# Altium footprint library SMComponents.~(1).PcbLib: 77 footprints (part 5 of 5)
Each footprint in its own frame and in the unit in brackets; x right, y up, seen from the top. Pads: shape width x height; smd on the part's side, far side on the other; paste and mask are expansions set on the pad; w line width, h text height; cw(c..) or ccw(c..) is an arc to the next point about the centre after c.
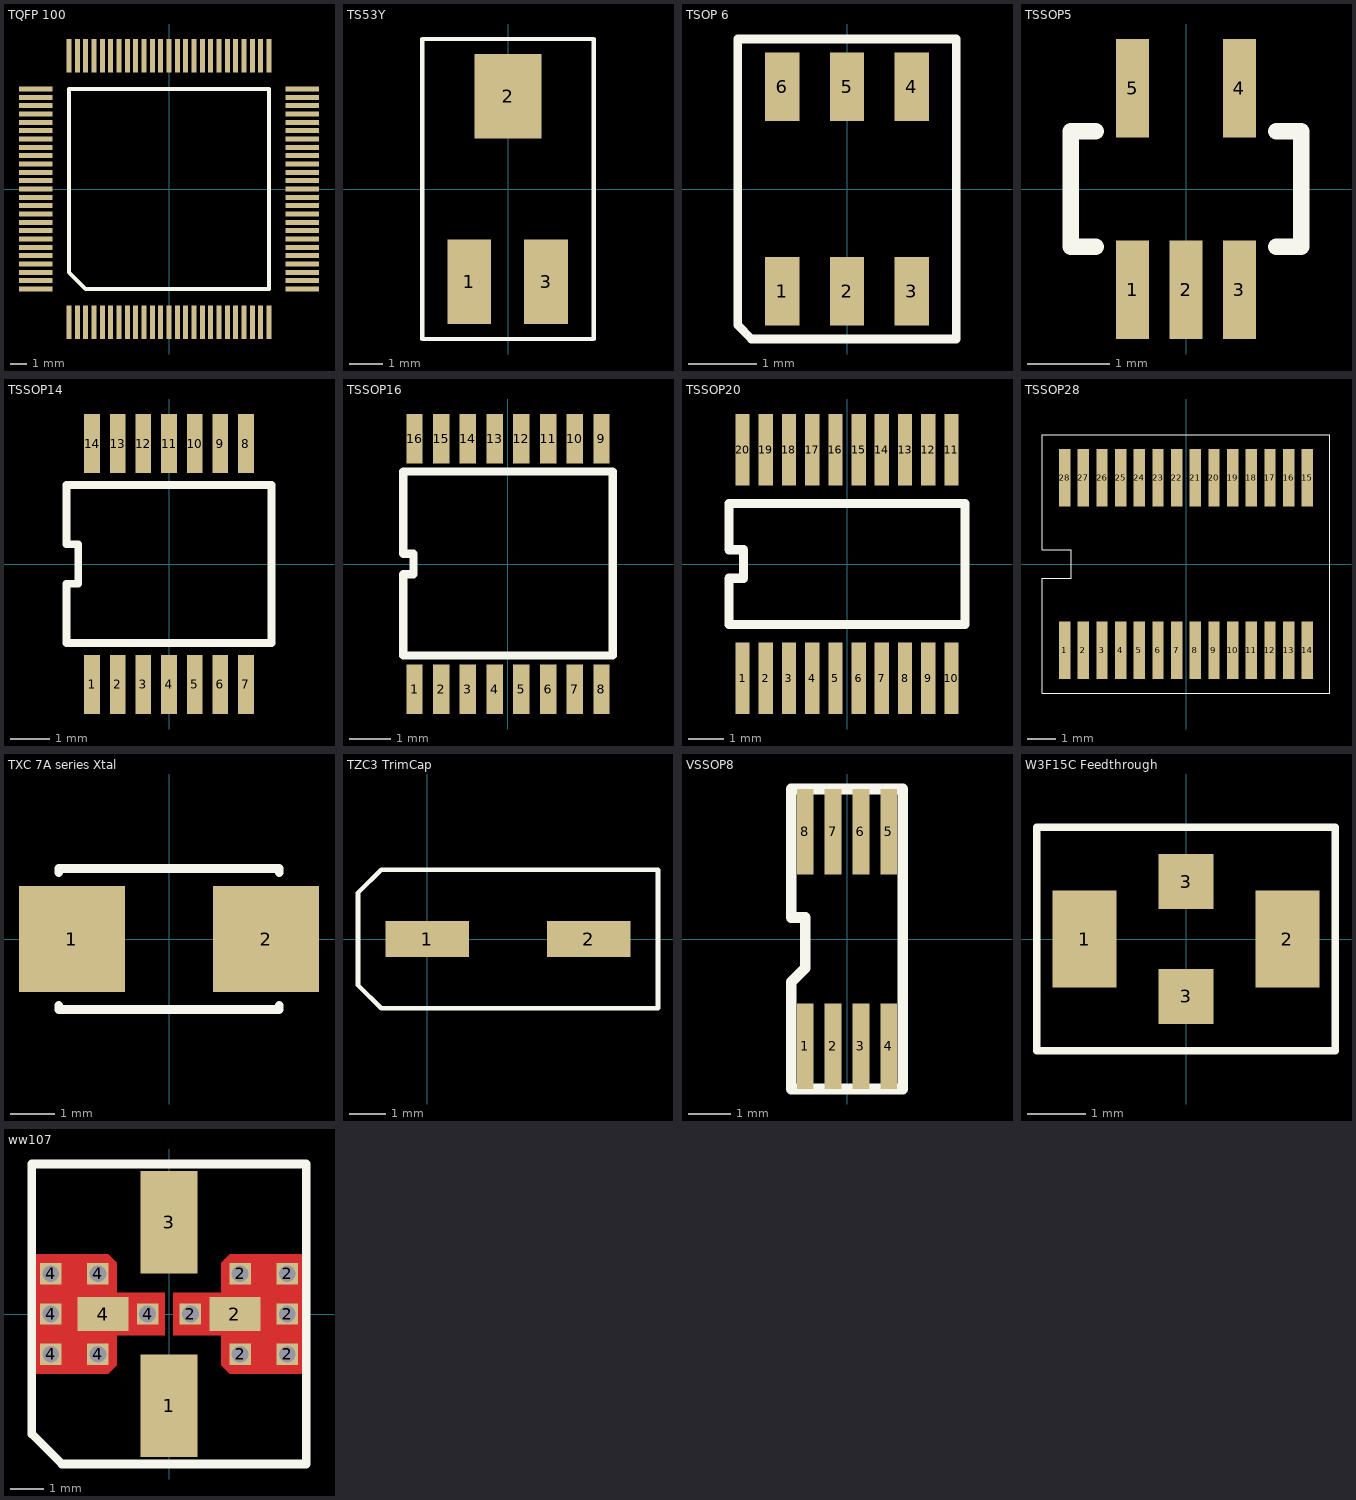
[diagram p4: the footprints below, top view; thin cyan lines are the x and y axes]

## TQFP 100 [mm] "Thin Quad Flat Pack - 100 pin 0.5mm pitch"
height 1.2
pads (100):
  rect 0.3x2 smd: 1(-6,-8) 2(-5.5,-8) 3(-5,-8) 4(-4.5,-8) 5(-4,-8) 6(-3.5,-8) 7(-3,-8) 8(-2.5,-8) 9(-2,-8) 10(-1.5,-8) 11(-1,-8) 12(-0.5,-8) 13(0,-8) 14(0.5,-8) 15(1,-8) 16(1.5,-8) 17(2,-8) 18(2.5,-8) 19(3,-8) 20(3.5,-8) 21(4,-8) 22(4.5,-8) 23(5,-8) 24(5.5,-8) 25(6,-8) 51(6,8) 52(5.5,8) 53(5,8) 54(4.5,8) 55(4,8) 56(3.5,8) 57(3,8) 58(2.5,8) 59(2,8) 60(1.5,8) 61(1,8) 62(0.5,8) 63(0,8) 64(-0.5,8) 65(-1,8) 66(-1.5,8) 67(-2,8) 68(-2.5,8) 69(-3,8) 70(-3.5,8) 71(-4,8) 72(-4.5,8) 73(-5,8) 74(-5.5,8) 75(-6,8)
  rect 2x0.3 smd: 26(8,-6) 27(8,-5.5) 28(8,-5) 29(8,-4.5) 30(8,-4) 31(8,-3.5) 32(8,-3) 33(8,-2.5) 34(8,-2) 35(8,-1.5) 36(8,-1) 37(8,-0.5) 38(8,0) 39(8,0.5) 40(8,1) 41(8,1.5) 42(8,2) 43(8,2.5) 44(8,3) 45(8,3.5) 46(8,4) 47(8,4.5) 48(8,5) 49(8,5.5) 50(8,6) 76(-8,6) 77(-8,5.5) 78(-8,5) 79(-8,4.5) 80(-8,4) 81(-8,3.5) 82(-8,3) 83(-8,2.5) 84(-8,2) 85(-8,1.5) 86(-8,1) 87(-8,0.5) 88(-8,0) 89(-8,-0.5) 90(-8,-1) 91(-8,-1.5) 92(-8,-2) 93(-8,-2.5) 94(-8,-3) 95(-8,-3.5) 96(-8,-4) 97(-8,-4.5) 98(-8,-5) 99(-8,-5.5) 100(-8,-6)
Top Overlay:
  lines w0.254: -6,-5 -6,6 6,6 6,-6 -5,-6 -6,-5

## TS53Y [mm] "TS53Y SM Pot Single Turn"
height 2.54
pads (3):
  rect 1.3x2.5 smd: 1(-1.15,-2.75) 3(1.13,-2.75)
  rect 2x2.5 smd: 2(0,2.75)
Top Overlay:
  lines w0.127: -2.54,-4.445 -2.54,4.445 2.54,4.445 2.54,-4.445 -2.54,-4.445

## TSOP 6 [mm] "TSOP 6 (JEDEC part no MO-193C)"
height 1.1
pads (6):
  rect 0.5x1 smd: 1(-0.95,-1.5) 2(0,-1.5) 3(0.95,-1.5) 4(0.95,1.5) 5(0,1.5) 6(-0.95,1.5)
Top Overlay:
  lines w0.127: -1.6,-2 -1.6,2.2 1.6,2.2 1.6,-2.2 -1.4,-2.2 -1.6,-2

## TSSOP5 [mm] "Plastic thin shrink small outline package. Body width 1.25mm"
height 1.1
pads (5):
  rect 0.4x1.2 smd: 1(-0.65,-1.225) 2(0,-1.225) 3(0.65,-1.225) 4(0.65,1.225) 5(-0.65,1.225)
Top Overlay:
  lines w0.2: -1.1,-0.7 -1.4,-0.7 -1.4,0.7 -1.1,0.7 ; 1.1,-0.7 1.4,-0.7 1.4,0.7 1.1,0.7

## TSSOP14 [mm]
pads (14):
  rect 0.4x1.5 smd: 1(-1.95,-3.05) 2(-1.3,-3.05) 3(-0.65,-3.05) 4(0,-3.05) 5(0.65,-3.05) 6(1.3,-3.05) 7(1.95,-3.05) 8(1.95,3.05) 9(1.3,3.05) 10(0.65,3.05) 11(0,3.05) 12(-0.65,3.05) 13(-1.3,3.05) 14(-1.95,3.05)
Top Overlay:
  lines w0.2: -2.6,-2 -2.6,-0.5 -2.3,-0.5 -2.3,0.5 -2.6,0.5 -2.6,2 2.6,2 2.6,-2 -2.6,-2

## TSSOP16 [mm]
height 1.5
pads (16):
  rect 0.4x1.2 smd: 1(-2.275,-3.05) 2(-1.625,-3.05) 3(-0.975,-3.05) 4(-0.325,-3.05) 5(0.325,-3.05) 6(0.975,-3.05) 7(1.625,-3.05) 8(2.275,-3.05) 9(2.275,3.05) 10(1.625,3.05) 11(0.975,3.05) 12(0.325,3.05) 13(-0.325,3.05) 14(-0.975,3.05) 15(-1.625,3.05) 16(-2.275,3.05)
Top Overlay:
  lines w0.2: -2.55,-2.225 -2.55,-0.25 -2.3,-0.25 -2.3,0.25 -2.55,0.25 -2.55,2.25 2.55,2.25 2.55,-2.225 -2.55,-2.225

## TSSOP20 [mm] "TSSOP20"
height 1.2
pads (20):
  rect 0.4x2 smd: 1(-2.925,-3.2) 2(-2.275,-3.2) 3(-1.625,-3.2) 4(-0.975,-3.2) 5(-0.325,-3.2) 6(0.325,-3.2) 7(0.975,-3.2) 8(1.625,-3.2) 9(2.275,-3.2) 10(2.925,-3.2) 11(2.925,3.2) 12(2.275,3.2) 13(1.625,3.2) 14(0.975,3.2) 15(0.325,3.2) 16(-0.325,3.2) 17(-0.975,3.2) 18(-1.625,3.2) 19(-2.275,3.2) 20(-2.925,3.2)
Top Overlay:
  lines w0.254: -3.3,-1.7 -3.3,-0.4 -2.9,-0.4 -2.9,0.4 -3.3,0.4 -3.3,1.7 3.3,1.7 3.3,-1.7 -3.3,-1.7

## TSSOP28 [mm] "TSSOP28"
pads (28):
  rect 0.395x2 smd: 1(-4.225,-3) 2(-3.575,-3) 3(-2.925,-3) 4(-2.275,-3) 5(-1.625,-3) 6(-0.975,-3) 7(-0.325,-3) 8(0.325,-3) 9(0.975,-3) 10(1.625,-3) 11(2.275,-3) 12(2.925,-3) 13(3.575,-3) 14(4.225,-3) 15(4.225,3) 16(3.575,3) 17(2.925,3) 18(2.275,3) 19(1.625,3) 20(0.975,3) 21(0.325,3) 22(-0.325,3) 23(-0.975,3) 24(-1.625,3) 25(-2.275,3) 26(-2.925,3) 27(-3.575,3) 28(-4.225,3)
Top Overlay:
  lines w0.025: -5,-4.5 5,-4.5 5,4.5 -5,4.5 -5,0.5 -4,0.5 -4,-0.5 -5,-0.5 -5,-4.5

## TXC 7A series Xtal [mm] "TXC 7A series Xtal"
pads (2):
  rect 2.4x2.4 smd: 1(-2.2,0) 2(2.2,0)
Top Overlay:
  lines w0.2: -2.5,-1.5 -2.5,-1.6 2.5,-1.6 2.5,-1.5 ; -2.5,1.5 -2.5,1.6 -2.4,1.6 2.5,1.6 2.5,1.5

## TZC3 TrimCap [mm] "Murata TZC3 trimmer Cap"
height 1.6
pads (2):
  rect 2.3x1 smd: 1(0,0) 2(4.445,0)
Top Overlay:
  lines w0.127: -1.905,-1.27 -1.905,1.27 -1.27,1.905 6.35,1.905 6.35,-1.905 -1.27,-1.905 -1.905,-1.27

## VSSOP8 [mm] "VSSOP8"
height 2
pads (8):
  rect 0.395x2 smd: 1(-0.975,-2.5) 2(-0.325,-2.5) 3(0.325,-2.5) 4(0.975,-2.5) 5(0.975,2.5) 6(0.325,2.5) 7(-0.325,2.5) 8(-0.975,2.5)
Top Overlay:
  lines w0.254: -1.3,-3.5 -1.3,-1 -0.975,-0.675 -0.975,-0.5 -0.975,0.5 -1.3,0.5 -1.3,3.5 1.3,3.5 1.3,-3.5 -1.3,-3.5

## W3F15C Feedthrough [mil] "Feedthrough (AVX)"
height 60
pads (4):
  rect 43x65 smd: 1(-68,0) 2(68,0)
  rect 37x37 smd: 3(0,-38.5) 3(0,38.5)
Top Overlay:
  lines w5: -100,-75 -100,75 100,75 100,-75 -100,-75

## ww107 [mil] "Mini circuits MAR-6SM"
height 78.74
pads (16):
  rect 66x120 smd: 1(0,-107) 3(0,107)
  rect 25x25 hole 19.68: 2(25,0) 2(83,-47) 2(83,47) 2(138,-47) 2(138,0) 2(138,47) 4(-138,-47) 4(-138,0) 4(-138,47) 4(-83,-47) 4(-83,47) 4(-25,0)
  rect 60x40 smd: 2(77,0) 4(-77,0)
Top Layer:
  region: 158,70 158,-70 71,-70 61,-60 61,-25 5,-25 5,25 61,25 61,60 71,70
  region: -158,70 -158,-70 -71,-70 -61,-60 -61,-25 -5,-25 -5,25 -61,25 -61,60 -71,70
Top Overlay:
  lines w10: -160,-140 -125,-175 160,-175 160,175 -160,175 -160,-140
Top Solder:
  rectangle: -65,-30 55,30
  rectangle: 55,-75 165,80
  rectangle: -165,-75 -55,75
